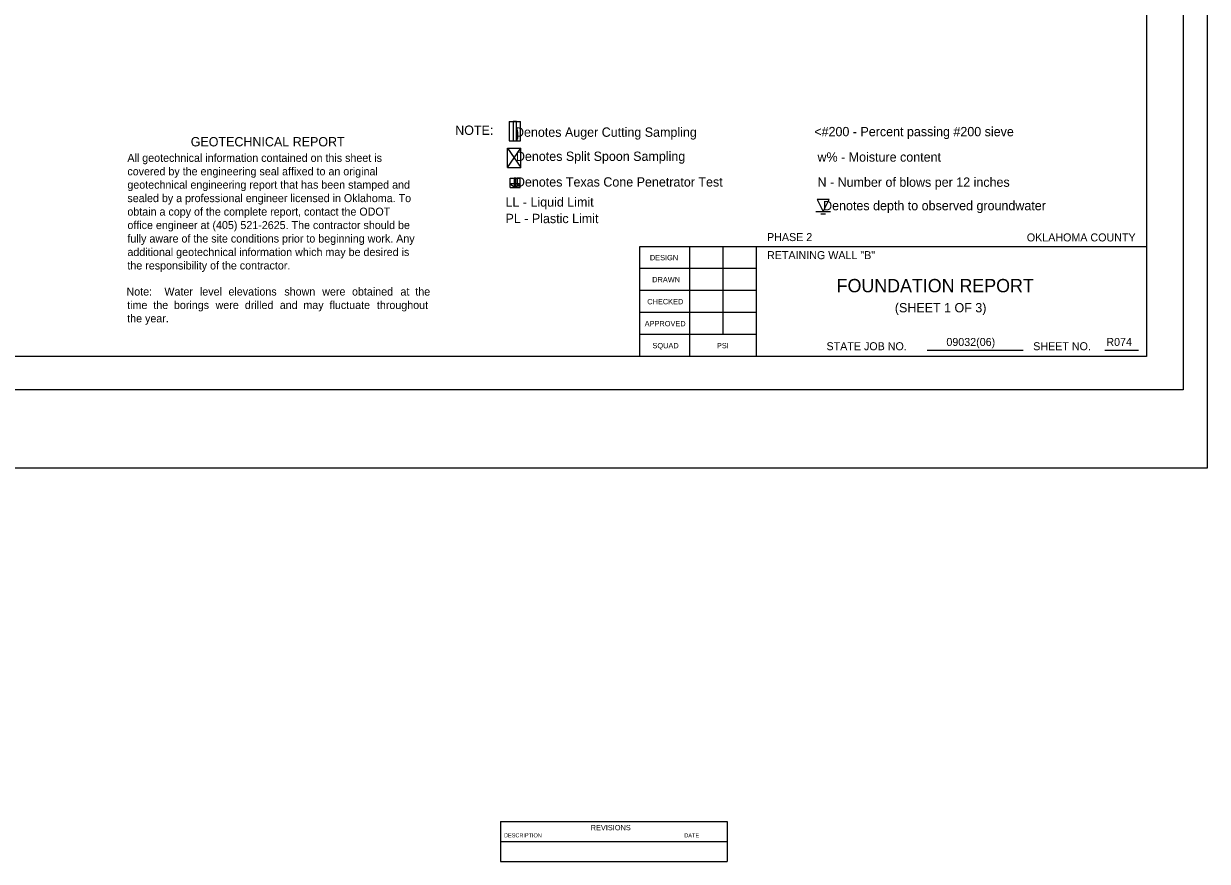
# Model space of a CAD drawing. Extents: x 7 to 126, y 24 to 56.
# Drawn here: x 24.87 to 42.62, y 24.08 to 36.64 of the extents above; entities that cross this region are included whole.
import ezdxf

# ---------------------------------------------------------------- set-up
doc = ezdxf.new("R2010")
doc.units = 0
for name, color, linetype in [('4', 7, 'Continuous'), ('REVBLK', 7, 'Continuous'), ('SHT_Plot_Shape_Full', 7, 'Continuous'), ('SHT_Plot_Shape_Half', 7, 'Continuous'), ('SHT_Sheet_Border', 7, 'Continuous'), ('SHT_Standard_Sheet_Lines', 7, 'Continuous'), ('SHT_Standard_Sheet_Txt', 7, 'Continuous'), ('T', 7, 'Continuous'), ('T-5', 7, 'Continuous'), ('Text', 7, 'Continuous')]:
    doc.layers.add(name, color=color, linetype=linetype)

# ---------------------------------------------------------------- blocks, each defined once
blk = doc.blocks.new('DGRFC_WTLEV1_1')
for points in [[(0, 0), (0.00417, 0.00833), (-0.00417, 0.00833), (0, 0)], [(-0.005, 0), (0.005, 0)], [(-0.00167, -0.00167), (0.00167, -0.00167)]]:
    blk.add_lwpolyline(points)

msp = doc.modelspace()

# ---------------------------------------------------------------- linework, layer by layer
msp.add_line((32.155, 35.172), (32.155, 34.881))
for points in [[(32.155, 35.172), (32.322, 35.172)], [(32.322, 34.881), (32.322, 35.172)], [(32.155, 34.881), (32.322, 34.881)], [(32.155, 34.881), (32.322, 34.881)]]:
    msp.add_lwpolyline(points)
for points in [[(32.213, 35.172), (32.213, 34.881), (32.263, 34.881), (32.263, 35.172)], [(32.278, 35.005), (32.272, 35.047), (32.263, 35.087), (32.278, 35.005)], [(32.263, 35.087), (32.263, 34.881), (32.278, 35.005), (32.263, 35.087)], [(32.263, 34.881), (32.278, 34.922), (32.278, 35.005), (32.263, 34.881)], [(32.278, 34.922), (32.28, 34.963), (32.278, 35.005), (32.278, 34.922)], [(32.263, 34.881), (32.272, 34.881), (32.278, 34.922), (32.263, 34.881)]]:
    msp.add_lwpolyline(points, close=True)
at = {"layer": 'REVBLK'}
for p, q in [((32.025, 24.676), (35.425, 24.676)), ((32.025, 24.676), (32.025, 24.076)), ((35.425, 24.676), (35.425, 24.076)), ((32.025, 24.376), (35.425, 24.376)), ((32.025, 24.076), (35.425, 24.076))]:
    msp.add_line(p, q, dxfattribs=at)
at = {"layer": 'SHT_Plot_Shape_Full'}
msp.add_lwpolyline([(6.624, 53.971), (42.624, 53.971), (42.624, 29.971), (6.624, 29.971)], close=True, dxfattribs=at)
at = {"layer": 'SHT_Plot_Shape_Half'}
msp.add_lwpolyline([(8.262, 53.146), (42.262, 53.146), (42.262, 31.146), (8.262, 31.146)], close=True, dxfattribs=at)
at = {"layer": 'SHT_Sheet_Border'}
for p, q in [((34.112, 31.646), (34.112, 33.296)), ((34.112, 33.296), (41.712, 33.296)), ((35.862, 31.646), (35.862, 33.297))]:
    msp.add_line(p, q, dxfattribs=at)
msp.add_lwpolyline([(10.212, 52.646), (41.712, 52.646), (41.712, 31.646), (10.212, 31.646)], close=True, dxfattribs=at)
at = {"layer": 'SHT_Standard_Sheet_Lines'}
for p, q in [((34.862, 31.646), (34.862, 33.297)), ((35.362, 31.976), (35.362, 33.297)), ((38.422, 31.742), (39.863, 31.742)), ((41.087, 31.742), (41.59, 31.742))]:
    msp.add_line(p, q, dxfattribs=at)
for points in [[(35.862, 32.966), (34.112, 32.966)], [(35.862, 32.636), (34.112, 32.636)], [(35.862, 32.306), (34.112, 32.306)], [(35.862, 31.976), (34.112, 31.976)]]:
    msp.add_lwpolyline(points, dxfattribs=at)
at = {"layer": 'Text'}
for p, q in [((32.131, 34.481), (32.131, 34.773)), ((32.167, 34.181), (32.167, 34.322))]:
    msp.add_line(p, q, dxfattribs=at)
for points in [[(32.131, 34.481), (32.331, 34.773)], [(32.131, 34.773), (32.331, 34.481)], [(32.131, 34.773), (32.331, 34.773)], [(32.331, 34.481), (32.331, 34.773)], [(32.131, 34.481), (32.331, 34.481)], [(32.167, 34.322), (32.317, 34.322)], [(32.317, 34.181), (32.317, 34.322)], [(32.167, 34.181), (32.317, 34.181)]]:
    msp.add_lwpolyline(points, dxfattribs=at)
for points in [[(32.227, 34.237), (32.257, 34.322), (32.227, 34.322), (32.227, 34.237)], [(32.227, 34.237), (32.257, 34.237), (32.257, 34.322), (32.227, 34.237)], [(32.227, 34.237), (32.167, 34.237), (32.242, 34.181), (32.227, 34.237)], [(32.227, 34.237), (32.242, 34.181), (32.257, 34.237), (32.227, 34.237)], [(32.242, 34.181), (32.317, 34.237), (32.257, 34.237), (32.242, 34.181)]]:
    msp.add_lwpolyline(points, close=True, dxfattribs=at)

# ---------------------------------------------------------------- block references
at = {"layer": 'Text', "xscale": 21.6, "yscale": 21.6}
msp.add_blockref('DGRFC_WTLEV1_1', (36.863, 33.823), dxfattribs=at)

# ---------------------------------------------------------------- texts
at = {"layer": '4'}
msp.add_text('FOUNDATION REPORT', height=0.2, dxfattribs=at).set_placement((37.065, 32.611))
at = {"layer": 'REVBLK'}
for s, height, p in [('REVISIONS', 0.08, (33.376, 24.542)), ('DESCRIPTION', 0.06, (32.077, 24.436)), ('DATE', 0.06, (34.781, 24.436))]:
    msp.add_text(s, height=height, dxfattribs=at).set_placement(p)
at = {"layer": 'SHT_Standard_Sheet_Txt'}
for s, height, p in [('DESIGN', 0.08, (34.264, 33.091)), ('DRAWN', 0.08, (34.299, 32.761)), ('CHECKED', 0.08, (34.225, 32.431)), ('APPROVED', 0.08, (34.186, 32.101)), ('SQUAD', 0.08, (34.303, 31.771)), ('PSI', 0.08, (35.27, 31.771)), ('STATE JOB NO.', 0.12, (36.913, 31.742)), ('SHEET NO. ', 0.12, (40.013, 31.742))]:
    msp.add_text(s, height=height, dxfattribs=at).set_placement(p)
at = {"layer": 'T'}
for s, p in [('PHASE 2', (36.021, 33.379)), ('OKLAHOMA COUNTY', (39.917, 33.374)), ('RETAINING WALL "B" ', (36.021, 33.108)), ('09032(06)', (38.711, 31.806)), ('R074', (41.11, 31.806))]:
    msp.add_text(s, height=0.12, dxfattribs=at).set_placement(p)
at = {"layer": 'T-5'}
msp.add_text('(SHEET 1 OF 3)', height=0.14, dxfattribs=at).set_placement((37.938, 32.31))
at = {"layer": 'Text'}
for s, height, p in [('NOTE:', 0.14, (31.344, 34.972)), ('    Denotes Auger Cutting Sampling', 0.14, (32.033, 34.943)), (' <#200 - Percent passing #200 sieve', 0.14, (36.678, 34.951)), ('GEOTECHNICAL REPORT', 0.14, (27.378, 34.799)), ('All geotechnical information contained on this sheet is ', 0.12, (26.428, 34.567)), ('    Denotes Split Spoon Sampling', 0.14, (32.047, 34.581)), ('w% - Moisture content', 0.14, (36.778, 34.57)), ('covered by the engineering seal affixed to an original ', 0.12, (26.428, 34.365)), ('geotechnical engineering report that has been stamped and ', 0.12, (26.428, 34.165)), ('    Denotes Texas Cone Penetrator Test', 0.14, (32.047, 34.196)), ('N - Number of blows per 12 inches', 0.14, (36.778, 34.193)), ('sealed by a professional engineer licensed in Oklahoma. To ', 0.12, (26.428, 33.963)), (' LL - Liquid Limit', 0.14, (32.047, 33.895)), ('    Denotes depth to observed groundwater', 0.14, (36.654, 33.841)), ('obtain a copy of the complete report, contact the ODOT ', 0.12, (26.428, 33.761)), (' PL - Plastic Limit', 0.14, (32.047, 33.648)), ('office engineer at (405) 521-2625. The contractor should be ', 0.12, (26.428, 33.559)), ('fully aware of the site conditions prior to beginning work. Any ', 0.12, (26.428, 33.357)), ('additional geotechnical information which may be desired is ', 0.12, (26.428, 33.155)), ('the responsibility of the contractor.', 0.12, (26.428, 32.953)), ('Note:', 0.12, (26.415, 32.562)), ('Water', 0.12, (26.983, 32.562)), ('level', 0.12, (27.516, 32.562)), ('elevations', 0.12, (27.944, 32.562)), ('shown', 0.12, (28.782, 32.562)), ('obtained', 0.12, (29.797, 32.562)), ('at', 0.12, (30.523, 32.562)), ('the ', 0.12, (30.746, 32.562)), ('time', 0.12, (26.425, 32.36)), ('the', 0.12, (26.817, 32.36)), ('borings', 0.12, (27.126, 32.36)), ('drilled', 0.12, (28.19, 32.36)), ('and', 0.12, (28.713, 32.36)), ('were', 0.12, (29.35, 32.562)), ('fluctuate', 0.12, (29.46, 32.36)), ('throughout ', 0.12, (30.17, 32.36)), ('were', 0.12, (27.751, 32.36)), ('may', 0.12, (29.068, 32.36)), ('the year.', 0.12, (26.425, 32.16))]:
    msp.add_text(s, height=height, dxfattribs=at).set_placement(p)

doc.saveas('drawing.dxf')
